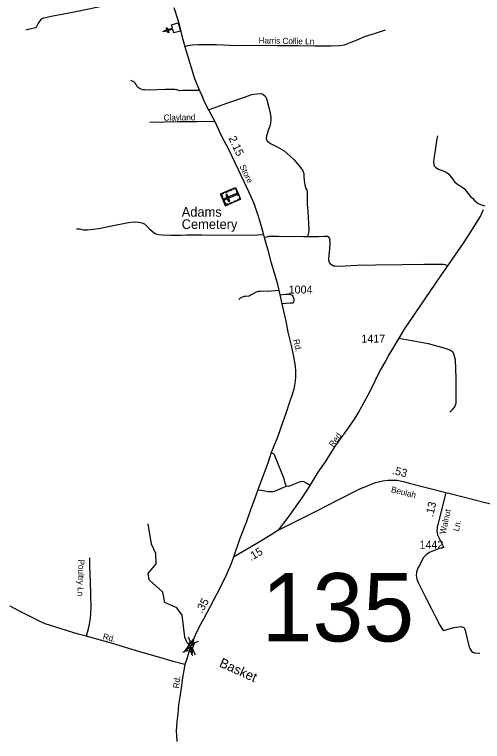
# Model space of a CAD drawing. Extents: x 2220236 to 2384410, y 720751 to 894131.
# Drawn here: x 2298391 to 2305697, y 820637 to 831981 of the extents above; entities that cross this region are included whole.
import ezdxf

# ---------------------------------------------------------------- set-up
doc = ezdxf.new("R2010")
doc.units = 0
doc.layers.add('Default', color=7, linetype='Continuous')

msp = doc.modelspace()

# ---------------------------------------------------------------- linework, layer by layer
at = {"layer": 'Default'}
for p, q in [((2301135, 822200), (2301107, 822263)), ((2301199, 822175), (2301262, 822203)), ((2301017, 822031), (2301080, 822059)), ((2301174, 821971), (2301146, 822034))]:
    msp.add_line(p, q, dxfattribs=at)
for points in [[(2300267, 832200), (2300045, 832165), (2299880, 832135), (2299322, 832018), (2298963, 831948), (2298879, 831932), (2298836, 831922), (2298808, 831907), (2298787, 831884), (2298755, 831836), (2298735, 831792), (2298716, 831774), (2298630, 831755), (2298565, 831735)], [(2300878, 832093), (2300940, 831900), (2300970, 831784), (2301003, 831649), (2301048, 831478), (2301147, 831153), (2301201, 830985), (2301223, 830933), (2301249, 830867), (2301277, 830797), (2301313, 830715), (2301342, 830651), (2301380, 830573), (2301421, 830496), (2301517, 830311), (2301624, 830085), (2301730, 829881), (2301970, 829375), (2302080, 829143), (2302124, 829050), (2302144, 828993), (2302186, 828867), (2302219, 828750), (2302257, 828621), (2302279, 828541), (2302290, 828499), (2302341, 828326), (2302395, 828122), (2302449, 827933), (2302495, 827774), (2302515, 827676), (2302531, 827607), (2302563, 827467), (2302625, 827197), (2302660, 827023), (2302712, 826814), (2302749, 826621), (2302773, 826488), (2302778, 826414), (2302779, 826332), (2302771, 826259), (2302753, 826136), (2302724, 826050), (2302689, 825946), (2302620, 825739), (2302555, 825550), (2302523, 825458), (2302490, 825371), (2302400, 825145), (2302349, 824998), (2302190, 824563), (2302138, 824418), (2302071, 824235), (2302005, 824053), (2301911, 823804), (2301807, 823515)], [(2304180, 831735), (2304006, 831678), (2303848, 831633), (2303762, 831592), (2303642, 831545), (2303536, 831503), (2303470, 831492), (2303336, 831488), (2303079, 831488), (2302826, 831495), (2302657, 831492), (2302490, 831491), (2302162, 831500), (2301862, 831494), (2301544, 831509), (2301262, 831510), (2301164, 831504), (2301092, 831495), (2301048, 831478)], [(2301277, 830797), (2301016, 830795), (2300968, 830792), (2300926, 830804), (2300892, 830810), (2300842, 830813), (2300744, 830812), (2300492, 830803), (2300422, 830805), (2300392, 830808), (2300366, 830814), (2300344, 830826), (2300324, 830839), (2300312, 830849), (2300290, 830889), (2300275, 830911), (2300251, 830931), (2300209, 830954)], [(2301421, 830496), (2301704, 830597), (2301979, 830690), (2302097, 830733), (2302173, 830744), (2302244, 830750), (2302265, 830737), (2302300, 830714), (2302314, 830695), (2302328, 830648), (2302357, 830553), (2302381, 830442), (2302390, 830376), (2302394, 830337), (2302388, 830284), (2302376, 830237), (2302357, 830186), (2302334, 830121), (2302325, 830087), (2302322, 830053), (2302325, 830021), (2302341, 830004), (2302372, 829980), (2302398, 829963), (2302492, 829914), (2302600, 829853), (2302689, 829777), (2302758, 829714), (2302803, 829657), (2302855, 829593), (2302890, 829540), (2302908, 829495), (2302909, 829451), (2302915, 829386), (2302925, 829321), (2302940, 829267), (2302953, 829238), (2302962, 829213), (2302960, 829162), (2302960, 829020), (2302969, 828908), (2302982, 828722), (2302985, 828619), (2302983, 828575), (2302974, 828548), (2302964, 828529), (2302948, 828510)], [(2301517, 830311), (2301235, 830306), (2300958, 830305), (2300502, 830298)], [(2304995, 830088), (2304981, 830015), (2304956, 829861), (2304935, 829733), (2304931, 829671), (2304945, 829622), (2304969, 829596), (2305008, 829568), (2305082, 829543), (2305120, 829526), (2305163, 829500), (2305229, 829417), (2305266, 829367), (2305326, 829320), (2305361, 829302), (2305415, 829259), (2305448, 829221), (2305512, 829142), (2305546, 829108), (2305579, 829073), (2305631, 829034), (2305666, 829016), (2305735, 828995)], [(2305710, 828931), (2305665, 828842), (2305603, 828743), (2305511, 828590), (2305397, 828412), (2305150, 828061), (2305043, 827902), (2304642, 827316), (2304474, 827073), (2304389, 826932), (2304233, 826673), (2304181, 826572), (2304099, 826432), (2303939, 826098), (2303847, 825928), (2303809, 825861), (2303760, 825774), (2303696, 825664), (2303589, 825515), (2303463, 825344), (2303385, 825236), (2303239, 825002), (2303126, 824839), (2303002, 824633), (2302875, 824439), (2302660, 824134), (2302505, 823935)], [(2302279, 828541), (2302091, 828535), (2301313, 828538), (2301075, 828538), (2300989, 828535), (2300832, 828534), (2300701, 828540), (2300641, 828544), (2300599, 828556), (2300569, 828567), (2300511, 828621), (2300469, 828668), (2300425, 828708), (2300384, 828724), (2300326, 828737), (2300257, 828740), (2300171, 828730), (2299933, 828683), (2299707, 828639), (2299528, 828616), (2299468, 828616), (2299407, 828629), (2299358, 828632)], [(2302948, 828510), (2302901, 828510), (2302512, 828517), (2302402, 828519), (2302360, 828515), (2302329, 828508), (2302290, 828499)], [(2303271, 828518), (2303226, 828519), (2303139, 828512), (2302948, 828510)], [(2303316, 828455), (2303316, 828456), (2303317, 828457), (2303317, 828458), (2303317, 828459), (2303317, 828460), (2303317, 828461), (2303317, 828462), (2303317, 828463), (2303317, 828464), (2303317, 828465), (2303317, 828466), (2303317, 828467), (2303317, 828468), (2303316, 828469), (2303316, 828470), (2303316, 828471), (2303316, 828472), (2303316, 828473), (2303316, 828474), (2303315, 828475), (2303315, 828476), (2303315, 828477), (2303315, 828478), (2303314, 828479), (2303314, 828480), (2303314, 828481), (2303313, 828482), (2303313, 828482), (2303313, 828483), (2303312, 828484), (2303312, 828485), (2303312, 828486), (2303311, 828487), (2303311, 828488), (2303310, 828489), (2303310, 828490), (2303309, 828491), (2303309, 828491), (2303308, 828492), (2303308, 828493), (2303307, 828494), (2303307, 828495), (2303306, 828496), (2303305, 828496), (2303305, 828497), (2303304, 828498), (2303304, 828499), (2303303, 828500), (2303302, 828500), (2303302, 828501), (2303301, 828502), (2303300, 828502), (2303300, 828503), (2303299, 828504), (2303298, 828505), (2303297, 828505), (2303297, 828506), (2303296, 828506), (2303295, 828507), (2303294, 828508), (2303293, 828508), (2303293, 828509), (2303292, 828509), (2303291, 828510), (2303290, 828511), (2303289, 828511), (2303288, 828512), (2303288, 828512), (2303287, 828513), (2303286, 828513), (2303285, 828513), (2303284, 828514), (2303283, 828514), (2303282, 828515), (2303281, 828515), (2303280, 828515), (2303279, 828516), (2303279, 828516), (2303278, 828516), (2303277, 828517), (2303276, 828517), (2303275, 828517), (2303274, 828518), (2303273, 828518), (2303272, 828518), (2303271, 828518)], [(2303300, 828167), (2303304, 828226), (2303313, 828322), (2303320, 828418), (2303316, 828455)], [(2303394, 828052), (2303393, 828052), (2303391, 828053), (2303389, 828053), (2303387, 828053), (2303385, 828054), (2303384, 828054), (2303382, 828054), (2303380, 828055), (2303378, 828055), (2303376, 828056), (2303375, 828056), (2303373, 828057), (2303371, 828057), (2303370, 828058), (2303368, 828058), (2303366, 828059), (2303364, 828060), (2303363, 828061), (2303361, 828061), (2303359, 828062), (2303358, 828063), (2303356, 828064), (2303355, 828065), (2303353, 828065), (2303351, 828066), (2303350, 828067), (2303348, 828068), (2303347, 828069), (2303345, 828070), (2303344, 828071), (2303342, 828072), (2303341, 828074), (2303339, 828075), (2303338, 828076), (2303337, 828077), (2303335, 828078), (2303334, 828079), (2303332, 828081), (2303331, 828082), (2303330, 828083), (2303329, 828085), (2303327, 828086), (2303326, 828087), (2303325, 828089), (2303324, 828090), (2303323, 828092), (2303321, 828093), (2303320, 828094), (2303319, 828096), (2303318, 828097), (2303317, 828099), (2303316, 828100), (2303315, 828102), (2303314, 828104), (2303313, 828105), (2303313, 828107), (2303312, 828108), (2303311, 828110), (2303310, 828112), (2303309, 828113), (2303309, 828115), (2303308, 828117), (2303307, 828118), (2303306, 828120), (2303306, 828122), (2303305, 828123), (2303305, 828125), (2303304, 828127), (2303304, 828129), (2303303, 828130), (2303303, 828132), (2303302, 828134), (2303302, 828136), (2303302, 828138), (2303301, 828139), (2303301, 828141), (2303301, 828143), (2303300, 828145), (2303300, 828147), (2303300, 828148), (2303300, 828150), (2303300, 828152), (2303300, 828154), (2303300, 828156), (2303300, 828158), (2303300, 828159), (2303300, 828161), (2303300, 828163), (2303300, 828165), (2303300, 828167)], [(2305150, 828061), (2305116, 828074), (2305083, 828079), (2305015, 828081), (2304779, 828082), (2304448, 828074), (2304029, 828068), (2303740, 828063), (2303554, 828056), (2303462, 828050), (2303394, 828052)], [(2302515, 827676), (2302343, 827660), (2302264, 827664), (2302226, 827661), (2302196, 827657), (2302166, 827649), (2302086, 827606), (2302052, 827585), (2301998, 827579), (2301972, 827579), (2301947, 827572), (2301913, 827556), (2301891, 827536)], [(2302531, 827607), (2302622, 827615), (2302684, 827618), (2302702, 827614), (2302726, 827602), (2302736, 827588), (2302753, 827542), (2302753, 827516), (2302747, 827486), (2302739, 827477), (2302714, 827477), (2302696, 827477), (2302630, 827474), (2302563, 827467)], [(2304389, 826932), (2304850, 826845), (2305096, 826780), (2305187, 826746), (2305215, 826732), (2305231, 826716), (2305245, 826691), (2305273, 826599), (2305281, 826301), (2305280, 825994), (2305279, 825912), (2305266, 825871), (2305229, 825816), (2305185, 825774)], [(2303002, 824633), (2302947, 824670), (2302913, 824688), (2302881, 824693), (2302851, 824689), (2302720, 824638), (2302694, 824627), (2302663, 824618), (2302632, 824622), (2302617, 824668), (2302599, 824734), (2302471, 825057), (2302451, 825109), (2302436, 825124), (2302400, 825145)], [(2302190, 824563), (2302235, 824556), (2302298, 824546), (2302350, 824538), (2302392, 824537), (2302423, 824537), (2302449, 824542), (2302502, 824565), (2302587, 824602), (2302632, 824622)], [(2302505, 823935), (2303111, 824235), (2303433, 824400), (2303773, 824576), (2304029, 824679), (2304139, 824702), (2304221, 824712), (2304301, 824716), (2304363, 824712), (2304482, 824688), (2304572, 824664), (2305126, 824523)], [(2305126, 824523), (2304990, 823977), (2304986, 823921), (2304994, 823862)], [(2305126, 824523), (2305190, 824504), (2305758, 824363), (2305926, 824324), (2306062, 824300), (2306134, 824282), (2306270, 824264), (2306441, 824249), (2306632, 824232), (2306855, 824212), (2307122, 824186), (2307593, 824129), (2307825, 824107)], [(2301216, 821985), (2301179, 822068), (2301141, 822118), (2301084, 822178), (2301052, 822267), (2301009, 822607), (2300925, 822722), (2300740, 822803), (2300705, 822969), (2300495, 823160), (2300477, 823258), (2300601, 823411), (2300599, 823568), (2300531, 823716), (2300477, 824032)], [(2302505, 823935), (2302423, 823875), (2302173, 823724), (2301807, 823515)], [(2304994, 823862), (2305095, 823664), (2305068, 823660), (2305020, 823646), (2304957, 823622), (2304881, 823589), (2304830, 823559), (2304807, 823540), (2304778, 823508), (2304754, 823470), (2304712, 823385), (2304694, 823353), (2304677, 823309), (2304668, 823284), (2304665, 823265), (2304662, 823231), (2304665, 823201), (2304673, 823170), (2304694, 823120), (2304808, 822887), (2304900, 822706), (2304956, 822594), (2305030, 822451), (2305071, 822384), (2305087, 822375), (2305096, 822375), (2305111, 822374), (2305128, 822378), (2305162, 822388), (2305255, 822413), (2305328, 822425), (2305359, 822429), (2305389, 822422), (2305408, 822415), (2305413, 822410), (2305423, 822391), (2305426, 822374), (2305436, 822327), (2305457, 822238), (2305484, 822128), (2305502, 822086), (2305514, 822061), (2305527, 822045), (2305547, 822029), (2305566, 822019), (2305582, 822019), (2305658, 822013)], [(2299561, 823502), (2299561, 823402), (2299563, 823370), (2299570, 823130), (2299578, 822925), (2299580, 822727), (2299576, 822641), (2299571, 822560), (2299555, 822467), (2299534, 822375), (2299508, 822279)], [(2301807, 823515), (2301766, 823399), (2301691, 823223), (2301639, 823110), (2301544, 822932), (2301339, 822546), (2301298, 822471), (2301233, 822343), (2301202, 822270), (2301135, 822096)], [(2301049, 821839), (2300870, 821885), (2300714, 821929), (2300331, 822043), (2300069, 822121), (2299941, 822159), (2299735, 822217), (2299508, 822279), (2299382, 822311), (2299200, 822367), (2298871, 822475), (2298811, 822499), (2298479, 822665), (2298322, 822747)], [(2301135, 822096), (2301128, 822080), (2301080, 821925), (2301049, 821839)], [(2301049, 821839), (2301015, 821631), (2300993, 821468), (2300970, 821334), (2300951, 821209), (2300938, 821062), (2300925, 820949), (2300919, 820873), (2300917, 820800), (2300918, 820734), (2300926, 820635)]]:
    msp.add_lwpolyline(points, dxfattribs=at)
for points in [[(2300878, 831696), (2300862, 831750), (2300789, 831730), (2300798, 831699), (2300782, 831694), (2300774, 831725), (2300716, 831709), (2300711, 831724), (2300769, 831741), (2300761, 831771), (2300776, 831776), (2300785, 831745), (2300858, 831766), (2300842, 831821), (2300945, 831850), (2300980, 831724)], [(2301687, 828998), (2301609, 829181), (2301843, 829281), (2301921, 829098)], [(2301856, 829250), (2301846, 829246), (2301837, 829266), (2301800, 829250), (2301796, 829261), (2301843, 829281)], [(2301649, 829198), (2301653, 829188), (2301624, 829175), (2301640, 829138), (2301629, 829133), (2301609, 829181)], [(2301671, 829110), (2301679, 829093), (2301865, 829172), (2301858, 829189)], [(2301721, 829216), (2301681, 829199), (2301676, 829210), (2301716, 829227)], [(2301734, 829062), (2301751, 829069), (2301705, 829178), (2301688, 829170)], [(2301781, 829242), (2301742, 829225), (2301737, 829236), (2301777, 829253)], [(2301888, 829146), (2301855, 829224), (2301866, 829229), (2301899, 829151)], [(2301658, 829066), (2301638, 829114), (2301648, 829118), (2301669, 829071)], [(2301727, 829015), (2301723, 829025), (2301693, 829013), (2301677, 829050), (2301667, 829046), (2301687, 828998)], [(2301795, 829044), (2301755, 829027), (2301751, 829037), (2301791, 829054)], [(2301857, 829070), (2301817, 829053), (2301813, 829064), (2301853, 829081)], [(2301908, 829128), (2301898, 829124), (2301906, 829103), (2301869, 829088), (2301874, 829077), (2301921, 829098)], [(2301043, 822033), (2301184, 822232), (2301161, 821989), (2301141, 822118)], [(2301080, 822059), (2301134, 822200), (2301200, 822175), (2301146, 822034)]]:
    msp.add_lwpolyline(points, close=True, dxfattribs=at)

# ---------------------------------------------------------------- texts
for s, height, rotation, p in [('Harris Collie Ln', 95, 358.8085, (2302200, 831531)), ('Clayland', 95, 0.7881, (2300719, 830325)), ('2.15', 125, 294.8932, (2301729, 830052)), ('Store', 95, 296.4459, (2301901, 829611)), ('Rd.', 95, 283.0776, (2302740, 826903)), ('Red', 95, 53.4003, (2303366, 825222)), ('.53', 125, 345.913, (2304278, 824814)), ('Beulah', 95, 346.1853, (2304263, 824528)), ('.13', 125, 77.0126, (2304925, 824135)), ('Walnut', 95, 76.6342, (2305116, 823864)), ('Ln.', 95, 78.4916, (2305328, 823909)), ('.15', 125, 30.2375, (2302080, 823449)), ('Poultry Ln', 95, 268.4318, (2299389, 823477)), ('.35', 125, 59.8939, (2301317, 822626)), ('Rd.', 95, 344.8757, (2299762, 822235)), ('Basket', 150, 335.8387, (2301575, 821810)), ('Rd.', 95, 83.4207, (2300959, 821461))]:
    msp.add_text(s, height=height, rotation=rotation, dxfattribs=at).set_placement(p)
for s, height, p in [('Adams', 150, (2301001, 828826)), ('Cemetery', 150, (2301001, 828635)), ('1004', 125, (2302671, 827627)), ('1417', 125, (2303806, 826860)), ('1442', 125, (2304714, 823645)), ('135', 1066.3, (2302250, 822198))]:
    msp.add_text(s, height=height, dxfattribs=at).set_placement(p)

doc.saveas('drawing.dxf')
